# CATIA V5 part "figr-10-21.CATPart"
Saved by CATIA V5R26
Part number: Part1
Bounding box of the stored display mesh (mm): x -60 to 60, y -90 to 70, z -46.082 to 16.155
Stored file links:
  D:\_Deepak\CATIA\CATIA V5-6R2016_Deepak\Resources\Part files\Partfiles\c10_catia_v5_6r2016_prt\figr-10-21.CATPart
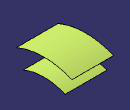
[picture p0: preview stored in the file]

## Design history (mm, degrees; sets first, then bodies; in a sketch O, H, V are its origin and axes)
Set1
  Sketch1 on yz-plane, origin (0, 0, 0), H (0, 1, 0), V (0, 0, 1)
    arc A1 centre (-10, -190) radius 206.1553 from (-90, 0) to (70, 0) cw
  Extrude1: Element1 Sketch1, Lim1 60, Lim2 60, Direction yz-plane
  Offset1: Offset Extrude1, Length 50
Body1 (main body)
